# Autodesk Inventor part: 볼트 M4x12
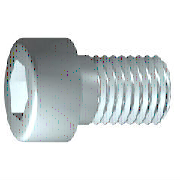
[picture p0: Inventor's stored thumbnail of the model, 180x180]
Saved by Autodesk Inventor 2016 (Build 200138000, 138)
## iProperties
IsCustomPart: 0
Created: 2012-02
Part Number: 볼트 M4x12
Material: 강철, 연강
Description: 6각 소켓 머리 캡 나사
Document SubType Name: Modeling
Standard: ISO 4762
Designer: mduedu
Standard Revision: Fourth edition 2004-03-01
Standards Organization: ISO
Language: ko-KR
Size Designation: M4 x 12
Categories: <MemberInstance><Categories><Category DisplayName="조임쇠" InternalName="e4da775c-781d-43d5-af7c-5136215cf5a6" Mnemonic="FSTN"><Category DisplayName="볼트" InternalN
Density: 7.75 g/cm^3
Appearance: 강철
Author: mduedu
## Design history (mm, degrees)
sketch "스케치1"
  geometry: L1 (-1, 0)-(12, 0); L2 (12, 0)-(12, 2); L3 (12, 2)-(1.75, 2); L4 (1.75, 2)-(1.32, 2); L5 (1.32, 2)-(0, 2); L6 (0, 2)-(0, 3.5); L7 (0, 3.5)-(-4, 3.5); L8 (-4, 3.5)-(-4, 1.732); L9 (-4, 1.732)-(-2, 1.732); L10 (-2, 1.732)-(-1, 0); L11 (-7.2, 0)-(15.2, 0) reference; L12 (0, -0.7)-(0, 4.2) reference; L13 (1.75, 2)-(0, 2)
  constraints: 22 end point, 6 parallel, 2 collinear, 2 perpendicular, 1 horizontal, 1 point on line
  dimensions: "d1" = 10.25 distance from line of L3.end L2 (= GEL); "d2" = 0.42952 distance of L4.end L3.end (computed from GAL); "d3" = 4 distance between parallel lines of L8 L6 (= KOH); "d4" = 2 distance of L8.end L9.end (= INTI); "d5" = 60 deg angle of L10 L1; "d6" = 4 diameter of L3 L1 (= GD); "d7" = 4 diameter of L5 L1 (= BDM); "d8" = 3.4641 diameter of L9 L1 (= 1.1547 x SW); "d9" = 7 diameter of L7 L1 (= KOD); "d26" = 12 distance between parallel lines of L12 L2 (= NLG)
revolve "본체" sketch "스케치1" stored, may be unused: angle "d10" = 90 deg
sketch "스케치2"
  geometry: L1 (0, -4.9)-(0, 4.9) reference; L2 (-4.9, 0)-(4.9, 0) reference; L3 (1.732, 0)-(0.866, -1.5); L4 (0.866, -1.5)-(-0.866, -1.5); L5 (-0.866, -1.5)-(-1.732, 0); L6 (-1.732, 0)-(-0.866, 1.5); L7 (-0.866, 1.5)-(0.866, 1.5); L8 (0.866, 1.5)-(1.732, 0); 2 further points
  constraints: 12 end point, 1 coincident, 1 horizontal alignment, 1 point on line, 12 other
extrude "슬롯" join sketch "스케치2" stored distance "d11" = 10; taper "d12" = 0 deg
workplane "Work Plane1"
fillet "Fillet2" dims "d30" = 0.1 (= R)
body "Solid1"
fillet "모깎기1" dims "d17" = 0.4 (= RR)
feature "스레드" dims "d13" = 10.25 (= GEL), "d14" = 0
chamfer "모따기1" distance "d15" = 0.42941 (= -0.5 x SPD + 0.5 x GD); stored, may be unused: second distance "d16" = 0.42941 (= GUL), angle "d27" = 45 deg
other parameters: "GD" = 4 [user parameter; used in 2 equation terms], "NLG" = 12 [user parameter; used in 1 equation term], "GEL" = 10.25 [user parameter; used in 2 equation terms], "KOD" = 7 [user parameter; used in 1 equation term], "KOH" = 4 [user parameter; used in 1 equation term], "INTI" = 2 [user parameter; used in 1 equation term], "GAL" = 0.42941 (= 0.61345 x PTC) [user parameter; used in 1 equation term], "GUL" = 0.42941 (= 0.61345 x PTC) [user parameter; used in 1 equation term], "BDM" = 4 (= NND) [user parameter; used in 1 equation term], "SW" = 3 [user parameter; used in 2 equation terms], "RR" = 0.4 [user parameter; used in 1 equation term], "SPD" = 3.14117 (= NND - 1.2269 x PTC) [user parameter; used in 1 equation term], "d19" = 0, "d28" = 0, "d29" = 0, "R" = 0.1 [user parameter; used in 1 equation term], "TOA" = 30 deg [user parameter], "GD1" = 3.14117 (= THREADDIA - 1.2269 x PTC) [user parameter], "THREADDIA" = 4 [user parameter; used in 1 equation term], "FAWI" = 45 deg [user parameter], "TPU" = 14.28571 (computed from PTC) [user parameter], "PTC" = 0.7 [user parameter; used in 5 equation terms], "NND" = 4 [user parameter; used in 2 equation terms], "E0" = 3.465 (= 1.155 x SW) [user parameter]
